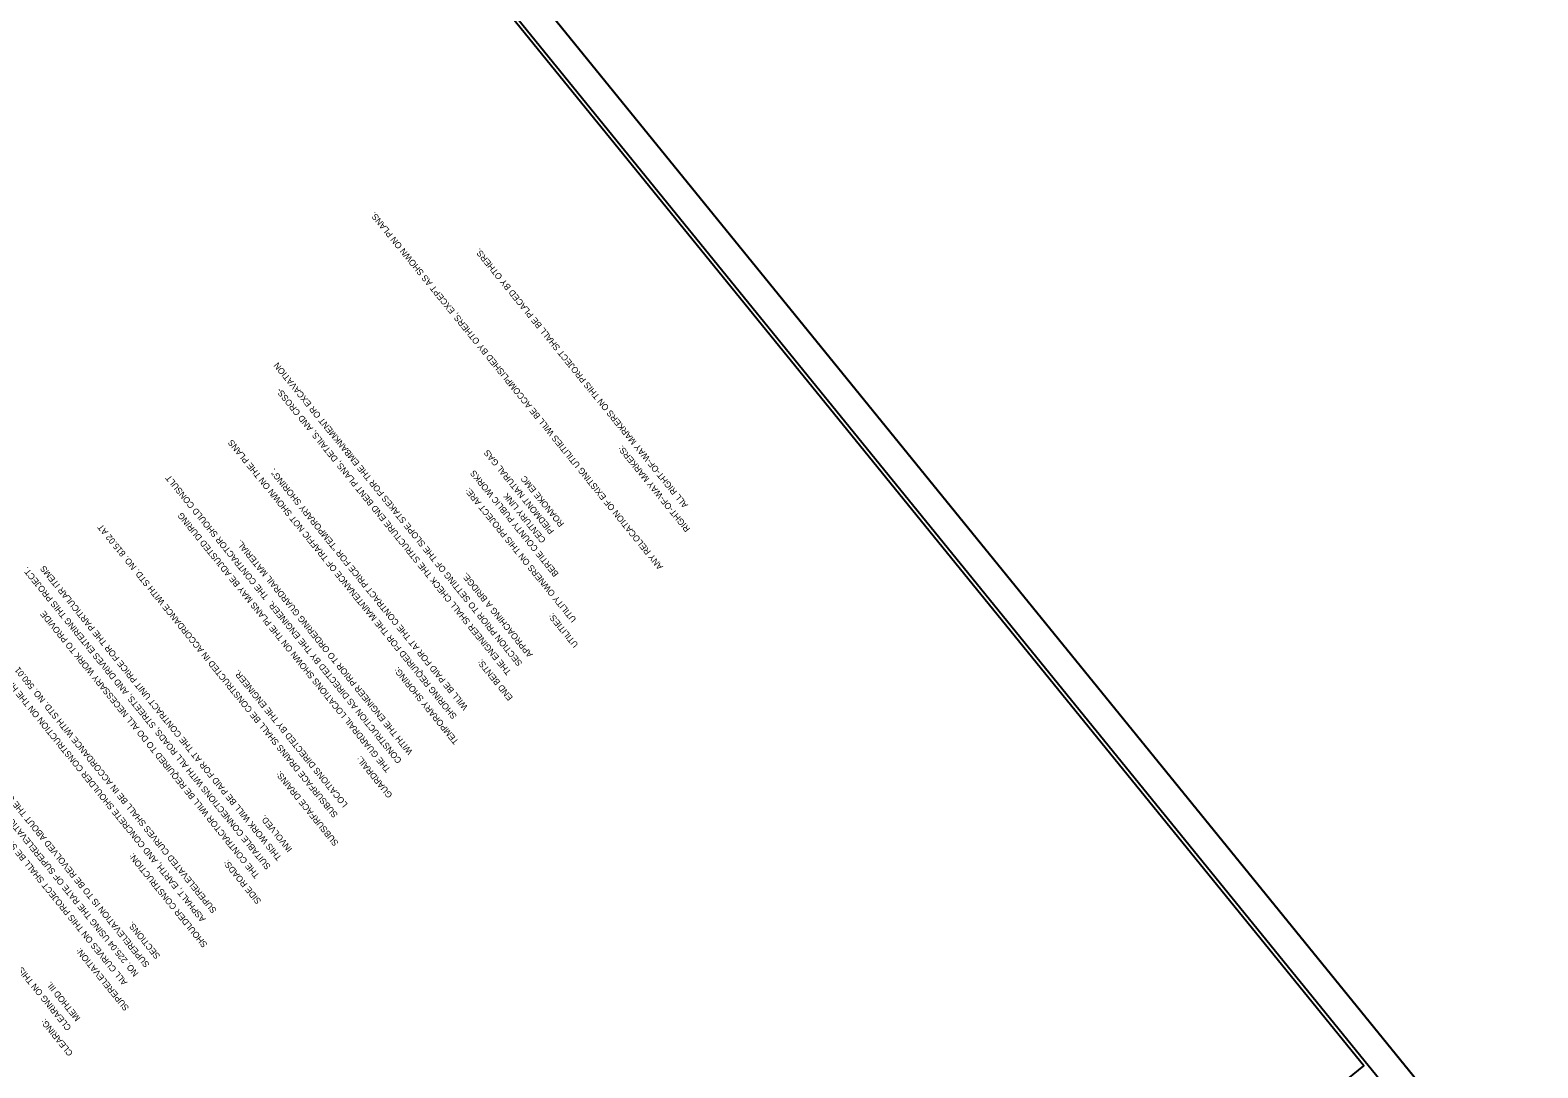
# Model space of a CAD drawing. Extents: x 2596486 to 2602076, y 851390 to 856110.
# Drawn here: x 2601014 to 2602076, y 853196 to 853927 of the extents above; entities that cross this region are included whole.
import ezdxf

# ---------------------------------------------------------------- set-up
doc = ezdxf.new("R2010")
doc.units = 0
for name, color, linetype in [('Sheet Cutting Line CELL', 7, 'Continuous'), ('Sheet Data Text CELL', 7, 'Continuous'), ('Sheet Plan CELL', 7, 'Continuous'), ('Sheet Plot Border Inside CELL', 7, 'Continuous'), ('Sheet Plot Border Outside CELL', 7, 'Continuous')]:
    doc.layers.add(name, color=color, linetype=linetype)

msp = doc.modelspace()

# ---------------------------------------------------------------- linework, layer by layer
at = {"layer": 'Sheet Cutting Line CELL'}
msp.add_line((2602075.7, 853082.8), (2601013.9, 854389.2), dxfattribs=at)
at = {"layer": 'Sheet Plan CELL'}
msp.add_line((2601953.2, 853197.8), (2601953.2, 853197.8), dxfattribs=at)
msp.add_lwpolyline([(2600192.4, 853699.5), (2601138.4, 852535.5), (2601953.2, 853197.8), (2601007.2, 854361.8)], close=True, dxfattribs=at)
at = {"layer": 'Sheet Plot Border Inside CELL'}
msp.add_lwpolyline([(2602052, 853080.2), (2601001.2, 854373.1), (2600182.5, 853707.7), (2601233.3, 852414.8)], close=True, dxfattribs=at)
at = {"layer": 'Sheet Plot Border Outside CELL'}
msp.add_lwpolyline([(2602075.7, 853082.8), (2601013.9, 854389.2), (2600164.2, 853698.5), (2601226, 852392.1)], close=True, dxfattribs=at)

# ---------------------------------------------------------------- texts
at = {"layer": 'Sheet Data Text CELL'}
for s, p in [('ANY RELOCATION OF EXISTING UTILITIES WILL BE ACCOMPLISHED BY OTHERS, EXCEPT AS SHOWN ON PLANS.', (2601459.7, 853549.4)), ('         ALL RIGHT-OF-WAY MARKERS ON THIS PROJECT SHALL BE PLACED BY OTHERS.  ', (2601486.6, 853581.5)), ('         SECTION PRIOR TO SETTING OF THE SLOPE STAKES FOR THE EMBANKMENT OR EXCAVATION ', (2601369.8, 853470.2)), ('         THE ENGINEER SHALL CHECK THE STRUCTURE END BENT PLANS, DETAILS, AND CROSS-', (2601362, 853463.9)), ('         SHORING REQUIRED FOR THE MAINTENANCE OF TRAFFIC NOT SHOWN ON THE PLANS ', (2601323.7, 853432.9)), ('PIEDMONT NATURAL GAS', (2601383, 853574.6)), ('RIGHT-OF-WAY MARKERS:  ', (2601478.8, 853576.1)), ('         CONSTRUCTION AS DIRECTED BY THE ENGINEER.  THE CONTRACTOR SHOULD CONSULT', (2601284.9, 853401.6)), ('         WILL BE PAID FOR AT THE CONTRACT PRICE FOR "TEMPORARY SHORING".', (2601331.5, 853439.2)), ('         BERTIE COUNTY PUBLIC WORKS', (2601395.4, 853533.1)), ('ROANOKE EMC', (2601390, 853579.7)), ('         UTILITY OWNERS ON THIS PROJECT ARE:', (2601407.9, 853501)), ('CENTURY LINK', (2601377.1, 853568.3)), ('         THE GUARDRAIL LOCATIONS SHOWN ON THE PLANS MAY BE ADJUSTED DURING ', (2601277.1, 853395.3)), ('         SUBSURFACE DRAINS SHALL BE CONSTRUCTED IN ACCORDANCE WITH STD. NO. 815.02 AT ', (2601239.9, 853363.4)), ('         WITH THE ENGINEER PRIOR TO ORDERING GUARDRAIL MATERIAL.', (2601292.6, 853407.8)), ('         SUITABLE CONNECTIONS WITH ALL ROADS, STREETS, AND DRIVES ENTERING THIS PROJECT.  ', (2601192.6, 853326.9)), ('         THIS WORK WILL BE PAID FOR AT THE CONTRACT UNIT PRICE FOR THE PARTICULAR ITEMS ', (2601200.3, 853333.2)), ('         APPROACHING A BRIDGE.  ', (2601377.3, 853476.2)), ('         THE CONTRACTOR WILL BE REQUIRED TO DO ALL NECESSARY WORK TO PROVIDE ', (2601184.7, 853320.6)), ('UTILITIES:  ', (2601400, 853494.6)), ('         ASPHALT, EARTH, AND CONCRETE SHOULDER CONSTRUCTION ON THE HIGH SIDE OF', (2601146.7, 853289.9)), ('END BENTS:  ', (2601353.9, 853457.3)), ('         SUPERELEVATION IS TO BE REVOLVED ABOUT THE GRADE POINTS SHOWN ON THE TYPICAL', (2601107.2, 853257.9)), ('         SUPERELEVATED CURVES SHALL BE IN ACCORDANCE WITH STD. NO. 560.01', (2601154.5, 853296.1)), ('         LOCATIONS DIRECTED BY THE ENGINEER.  ', (2601246.8, 853370.7)), ('TEMPORARY SHORING:  ', (2601315.7, 853426.4)), ('         NO. 225.04 USING THE RATE OF SUPERELEVATION AND RUNOFF SHOWN ON THE PLANS.', (2601099.4, 853251.6)), ('         ALL CURVES ON THIS PROJECT SHALL BE SUPERELEVATED IN ACCORDANCE WITH STD.', (2601091.6, 853245.3)), ('         CLEARING ON THIS PROJECT SHALL BE PERFORMED TO THE LIMITS ESTABLISHED BY ', (2601052.1, 853213.4)), ('GUARDRAIL:  ', (2601269.1, 853388.7)), ('SUBSURFACE DRAINS:  ', (2601231.1, 853354.9)), ('         INVOLVED.  ', (2601207.8, 853339.2)), ('SHOULDER CONSTRUCTION:  ', (2601138.7, 853283.4)), ('SIDE ROADS:  ', (2601176.6, 853314)), ('         SECTIONS.  ', (2601114.7, 853263.9)), ('SUPERELEVATION:  ', (2601083.5, 853238.8)), ('         METHOD III.', (2601058.5, 853220.1)), ('CLEARING:  ', (2601044, 853206.9))]:
    msp.add_text(s, height=4.4, rotation=129.1028, dxfattribs=at).set_placement(p)

doc.saveas('drawing.dxf')
